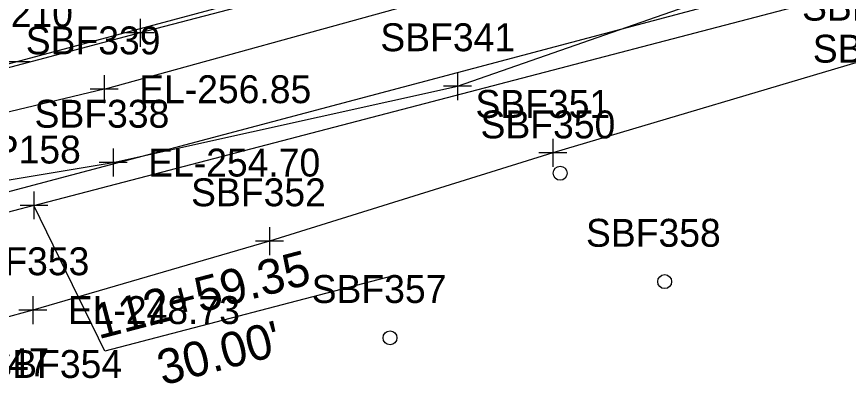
# Model space of a CAD drawing. Extents: x 818717 to 846077, y 440014 to 541392.
# Drawn here: x 832182.9 to 832302.2, y 493175.5 to 493229.4 of the extents above; entities that cross this region are included whole.
import ezdxf

# ---------------------------------------------------------------- set-up
doc = ezdxf.new("R2010")
doc.units = 0
for name, color, linetype in [('SURVEY - DTM - Breaklines', 7, 'Continuous'), ('SURVEY - DTM - Breaklines - Points - Elevations', 7, 'Continuous'), ('SURVEY - DTM - Breaklines - Points - Locators', 7, 'Continuous'), ('SURVEY - DTM - Breaklines - Points - Numbers', 7, 'Continuous'), ('SURVEY - DTM - Spot Points - Locators', 7, 'Continuous'), ('SURVEY - DTM - Spot Points - Point Numbers', 7, 'Continuous'), ('SURVEY - PROPERTY - ROW Lines', 7, 'Continuous'), ('SURVEY - PROPERTY - ROW Lines - Points - Locators', 7, 'Continuous'), ('SURVEY - PROPERTY - ROW Lines - Points - Numbers', 7, 'Continuous'), ('SURVEY - PROPERTY - Station and Offset Flags', 7, 'Continuous'), ('SURVEY - TRAFFIC CONTROL - Pavement Marking - Points - Locators', 7, 'Continuous'), ('SURVEY - TRAFFIC CONTROL - Pavement Marking - Points - Numbers', 7, 'Continuous'), ('SURVEY - TRAFFIC CONTROL - Pavement Marking with Text', 7, 'Continuous'), ('SURVEY - TRANSPORTATION - Roads', 7, 'Continuous'), ('SURVEY - TRANSPORTATION - Roads - Points - Locators', 7, 'Continuous'), ('SURVEY - UTILITIES - Electric (Overhead) with Text', 7, 'Continuous')]:
    doc.layers.add(name, color=color, linetype=linetype)

msp = doc.modelspace()

# ---------------------------------------------------------------- linework, layer by layer
at = {"layer": 'SURVEY - DTM - Breaklines'}
for points in [[(832195.49, 493218.96), (832241.6, 493231.67), (832290.32, 493240.18), (832343.91, 493258.96)], [(832151.95, 493201.02), (832196.78, 493208.44), (832246.16, 493219.41), (832291.57, 493235.26), (832344.85, 493247.44)], [(832358.47, 493237.07), (832306.82, 493223.8), (832259.81, 493209.85), (832219.18, 493197.18), (832185.26, 493187.29), (832157.93, 493179.81)], [(832195.49, 493218.96), (832149.66, 493208), (832104.44, 493192.76), (832056.4, 493179.89), (832008.79, 493165.69), (831963, 493154.57), (831916.73, 493144.05), (831869.5, 493130.85), (831832.06, 493121.28), (831826.36, 493121.02)]]:
    msp.add_lwpolyline(points, dxfattribs=at)
at = {"layer": 'SURVEY - DTM - Breaklines - Points - Locators'}
for p, q in [((832195.49, 493220.96), (832195.49, 493216.96)), ((832195.49, 493220.96), (832195.49, 493216.96)), ((832246.16, 493221.41), (832246.16, 493217.41)), ((832248.16, 493219.41), (832244.16, 493219.41)), ((832197.49, 493218.96), (832193.49, 493218.96)), ((832197.49, 493218.96), (832193.49, 493218.96)), ((832259.81, 493211.85), (832259.81, 493207.85)), ((832196.78, 493210.44), (832196.78, 493206.44)), ((832261.81, 493209.85), (832257.81, 493209.85)), ((832198.78, 493208.44), (832194.78, 493208.44)), ((832219.18, 493199.18), (832219.18, 493195.18)), ((832221.18, 493197.18), (832217.18, 493197.18)), ((832185.26, 493189.29), (832185.26, 493185.29)), ((832187.26, 493187.29), (832183.26, 493187.29))]:
    msp.add_line(p, q, dxfattribs=at)
at = {"layer": 'SURVEY - DTM - Spot Points - Locators'}
for centre in [(832260.86, 493206.91), (832275.86, 493191.37), (832236.47, 493183.31)]:
    msp.add_circle(centre, 1, dxfattribs=at)
at = {"layer": 'SURVEY - PROPERTY - ROW Lines'}
msp.add_line((832185.41, 493202.31), (832544.06, 493295.97), dxfattribs=at)
msp.add_arc((846074.62, 440015.93), 54970, 104.635499, 105.043649, dxfattribs=at)
at = {"layer": 'SURVEY - PROPERTY - ROW Lines - Points - Locators'}
for p, q in [((832185.41, 493204.31), (832185.41, 493200.31)), ((832185.41, 493204.31), (832185.41, 493200.31)), ((832187.41, 493202.31), (832183.41, 493202.31)), ((832187.41, 493202.31), (832183.41, 493202.31))]:
    msp.add_line(p, q, dxfattribs=at)
at = {"layer": 'SURVEY - PROPERTY - Station and Offset Flags'}
msp.add_line((832236.9, 493192.19), (832195.55, 493181.39), dxfattribs=at)
msp.add_lwpolyline([(832195.55, 493181.39), (832185.41, 493202.31)], dxfattribs=at)
at = {"layer": 'SURVEY - TRAFFIC CONTROL - Pavement Marking - Points - Locators'}
msp.add_line((832184.8, 493222.89), (832180.8, 493222.89), dxfattribs=at)
at = {"layer": 'SURVEY - TRAFFIC CONTROL - Pavement Marking with Text'}
msp.add_lwpolyline([(832086.82, 493197.77), (832134.83, 493210.3), (832182.8, 493222.89), (832231.22, 493235.87), (832279.2, 493248.14), (832327.01, 493260.84), (832342.88, 493265)], dxfattribs=at)
at = {"layer": 'SURVEY - TRANSPORTATION - Roads'}
msp.add_lwpolyline([(832342.92, 493264.27), (832295.67, 493251.85), (832250.01, 493239.95), (832200.63, 493227.05), (832152.17, 493214.17), (832103.93, 493201.62), (832054.77, 493188.77), (832008.06, 493176.05), (831961.15, 493163.88), (831914.15, 493151.63), (831865.83, 493138.65), (831819.22, 493125.71), (831773.59, 493113.35)], dxfattribs=at)
at = {"layer": 'SURVEY - TRANSPORTATION - Roads - Points - Locators'}
for p, q in [((832200.63, 493229.05), (832200.63, 493225.05)), ((832202.63, 493227.05), (832198.63, 493227.05))]:
    msp.add_line(p, q, dxfattribs=at)
at = {"layer": 'SURVEY - UTILITIES - Electric (Overhead) with Text'}
msp.add_lwpolyline([(832667.18, 493331.74), (832415.28, 493266.23), (832147.85, 493195.27), (831907.96, 493131.64), (831666.03, 493064.14), (831375.19, 492986.65), (831101.3, 492913.04)], dxfattribs=at)

# ---------------------------------------------------------------- texts
at = {"layer": 'SURVEY - DTM - Breaklines - Points - Elevations'}
for s, p in [('EL-256.85', (832200.49, 493216.96)), ('EL-254.70', (832201.78, 493206.44)), ('EL-248.73', (832190.26, 493185.29)), ('EL-249.47', (832162.93, 493177.81))]:
    msp.add_text(s, height=4, dxfattribs=at).set_placement(p)
at = {"layer": 'SURVEY - DTM - Breaklines - Points - Numbers'}
for s, p in [('SBF349', (832295.56, 493228.8)), ('SBF339', (832184.23, 493223.96)), ('SBF339', (832184.23, 493223.96)), ('SBF341', (832235.08, 493224.41)), ('SBF351', (832248.72, 493214.85)), ('SBF338', (832185.49, 493213.44)), ('SBF352', (832207.94, 493202.18)), ('SBF353', (832174.02, 493192.29))]:
    msp.add_text(s, height=4, dxfattribs=at).set_placement(p)
at = {"layer": 'SURVEY - DTM - Spot Points - Point Numbers'}
for s, p in [('SBF348', (832297.1, 493222.77)), ('SBF350', (832249.45, 493211.91)), ('SBF358', (832264.57, 493196.37)), ('SBF357', (832225.23, 493188.31)), ('SBF354', (832178.72, 493177.56))]:
    msp.add_text(s, height=4, dxfattribs=at).set_placement(p)
at = {"layer": 'SURVEY - PROPERTY - ROW Lines - Points - Numbers'}
msp.add_text('SP158', height=4, dxfattribs=at).set_placement((832176.07, 493208.31))
at = {"layer": 'SURVEY - PROPERTY - Station and Offset Flags'}
for s, p in [('112+59.35', (832194.66, 493183.09)), ("30.00'", (832203.87, 493176.46))]:
    msp.add_text(s, height=5, rotation=14.6355, dxfattribs=at).set_placement(p)
at = {"layer": 'SURVEY - TRAFFIC CONTROL - Pavement Marking - Points - Numbers'}
msp.add_text('SRF210', height=4, dxfattribs=at).set_placement((832171.38, 493227.89))

doc.saveas('drawing.dxf')
